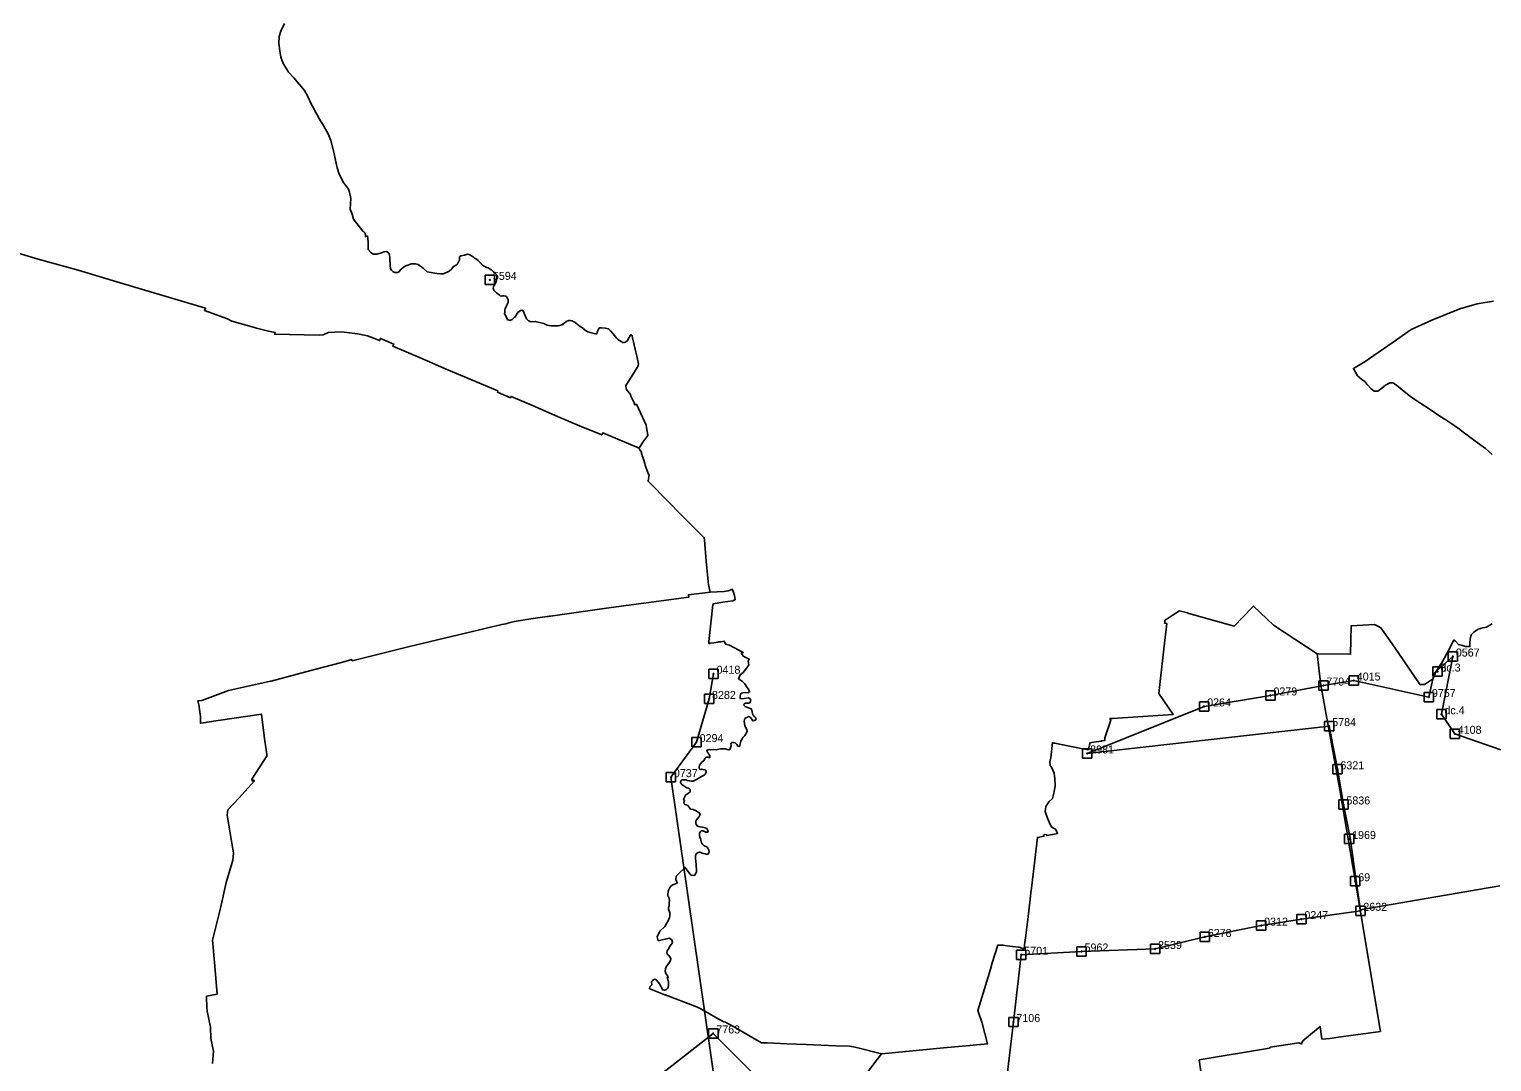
# Model space of a CAD drawing. Extents: x 462479 to 502016, y 241775 to 305873.
# Drawn here: x 475403 to 486368, y 272494 to 280240 of the extents above; entities that cross this region are included whole.
import ezdxf

# ---------------------------------------------------------------- set-up
doc = ezdxf.new("R2010")
doc.units = 0
for name, color, linetype in [('Default', 7, 'Continuous'), ('Level 19', 7, 'Continuous'), ('Level 51', 7, 'Continuous'), ('novada_robeza', 7, 'Continuous'), ('pagastu_robezas', 7, 'Continuous')]:
    doc.layers.add(name, color=color, linetype=linetype)

msp = doc.modelspace()

# ---------------------------------------------------------------- linework, layer by layer
at = {"layer": 'Default'}
for points in [[(466551, 278322), (476083, 271265), (477799, 272087), (478457, 271911), (479001, 271766), (479184, 271750), (479406, 271913), (479591, 272067), (480062, 272337), (480532, 272706), (480863, 272374), (480572, 271840), (481408, 272070), (480814, 270463), (480214, 274629), (480407, 274892), (480500, 275216), (480534, 275405)], [(482721, 272268), (482782, 272792), (482841, 273296), (483293, 273321), (483844, 273340), (484217, 273430), (484639, 273515), (484941, 273564), (485383, 273626), (485352, 273852), (485307, 274173), (485256, 274424), (485211, 274688), (485150, 275012), (483335, 274807), (484212, 275160), (484709, 275242), (485106, 275316), (485334, 275354), (485897, 275230), (485936, 275408), (486077, 275534), (485991, 275101), (486091, 274954), (486436, 274835)]]:
    msp.add_lwpolyline(points, dxfattribs=at)
at = {"layer": 'Level 19'}
for p, q in [((478822, 278395), (478892, 278395)), ((478822, 278325), (478822, 278395)), ((478892, 278325), (478822, 278325)), ((478892, 278395), (478892, 278325)), ((486041, 275569), (486111, 275569)), ((486041, 275499), (486041, 275569)), ((486042, 275569), (486112, 275569)), ((486042, 275499), (486042, 275569)), ((486111, 275569), (486111, 275499)), ((486112, 275569), (486112, 275499)), ((485926, 275456), (485996, 275456)), ((485926, 275386), (485926, 275456)), ((485926, 275456), (485996, 275456)), ((485926, 275386), (485926, 275456)), ((485926, 275456), (485996, 275456)), ((485926, 275386), (485926, 275456)), ((485927, 275456), (485997, 275456)), ((485927, 275386), (485927, 275456)), ((485996, 275456), (485996, 275386)), ((485996, 275456), (485996, 275386)), ((485996, 275456), (485996, 275386)), ((485997, 275456), (485997, 275386)), ((486111, 275499), (486041, 275499)), ((486112, 275499), (486042, 275499)), ((480499, 275440), (480569, 275440)), ((480499, 275370), (480499, 275440)), ((480569, 275370), (480499, 275370)), ((480569, 275440), (480569, 275370)), ((485071, 275351), (485141, 275351)), ((485071, 275281), (485071, 275351)), ((485071, 275351), (485141, 275351)), ((485071, 275281), (485071, 275351)), ((485071, 275351), (485141, 275351)), ((485071, 275281), (485071, 275351)), ((485071, 275351), (485141, 275351)), ((485071, 275281), (485071, 275351)), ((485141, 275351), (485141, 275281)), ((485141, 275351), (485141, 275281)), ((485141, 275351), (485141, 275281)), ((485141, 275351), (485141, 275281)), ((485299, 275389), (485369, 275389)), ((485299, 275319), (485299, 275389)), ((485369, 275389), (485369, 275319)), ((485996, 275386), (485926, 275386)), ((485996, 275386), (485926, 275386)), ((485996, 275386), (485926, 275386)), ((485997, 275386), (485927, 275386)), ((480465, 275251), (480535, 275251)), ((480465, 275181), (480465, 275251)), ((480535, 275251), (480535, 275181)), ((484674, 275277), (484744, 275277)), ((484674, 275207), (484674, 275277)), ((484744, 275277), (484744, 275207)), ((485141, 275281), (485071, 275281)), ((485141, 275281), (485071, 275281)), ((485141, 275281), (485071, 275281)), ((485141, 275281), (485071, 275281)), ((485369, 275319), (485299, 275319)), ((485862, 275265), (485932, 275265)), ((485862, 275195), (485862, 275265)), ((485862, 275265), (485932, 275265)), ((485862, 275195), (485862, 275265)), ((485862, 275265), (485932, 275265)), ((485862, 275195), (485862, 275265)), ((485932, 275265), (485932, 275195)), ((485932, 275265), (485932, 275195)), ((485932, 275265), (485932, 275195)), ((480535, 275181), (480465, 275181)), ((484177, 275195), (484247, 275195)), ((484177, 275125), (484177, 275195)), ((484247, 275125), (484177, 275125)), ((484247, 275195), (484247, 275125)), ((484744, 275207), (484674, 275207)), ((485932, 275195), (485862, 275195)), ((485932, 275195), (485862, 275195)), ((485932, 275195), (485862, 275195)), ((485956, 275136), (486026, 275136)), ((485956, 275066), (485956, 275136)), ((486026, 275136), (486026, 275066)), ((485115, 275047), (485185, 275047)), ((485115, 274977), (485115, 275047)), ((485185, 275047), (485185, 274977)), ((486026, 275066), (485956, 275066)), ((480372, 274927), (480442, 274927)), ((480372, 274857), (480372, 274927)), ((480442, 274927), (480442, 274857)), ((485185, 274977), (485115, 274977)), ((486056, 274989), (486126, 274989)), ((486056, 274919), (486056, 274989)), ((486056, 274989), (486126, 274989)), ((486056, 274919), (486056, 274989)), ((486056, 274989), (486126, 274989)), ((486056, 274919), (486056, 274989)), ((486126, 274919), (486056, 274919)), ((486126, 274919), (486056, 274919)), ((486126, 274919), (486056, 274919)), ((486126, 274989), (486126, 274919)), ((486126, 274989), (486126, 274919)), ((486126, 274989), (486126, 274919)), ((480442, 274857), (480372, 274857)), ((483300, 274842), (483370, 274842)), ((483300, 274772), (483300, 274842)), ((483370, 274842), (483370, 274772)), ((483370, 274772), (483300, 274772)), ((485176, 274723), (485246, 274723)), ((485176, 274653), (485176, 274723)), ((485246, 274723), (485246, 274653)), ((480179, 274664), (480249, 274664)), ((480179, 274594), (480179, 274664)), ((480249, 274594), (480179, 274594)), ((480249, 274664), (480249, 274594)), ((485246, 274653), (485176, 274653)), ((485221, 274459), (485291, 274459)), ((485221, 274389), (485221, 274459)), ((485291, 274459), (485291, 274389)), ((485291, 274389), (485221, 274389)), ((485264, 274200), (485334, 274200)), ((485264, 274130), (485264, 274200)), ((485334, 274130), (485264, 274130)), ((485334, 274200), (485334, 274130)), ((485310, 273883), (485380, 273883)), ((485310, 273813), (485310, 273883)), ((485380, 273813), (485310, 273813)), ((485380, 273883), (485380, 273813)), ((484906, 273599), (484976, 273599)), ((484906, 273529), (484906, 273599)), ((484976, 273599), (484976, 273529)), ((485348, 273661), (485418, 273661)), ((485348, 273591), (485348, 273661)), ((485418, 273591), (485348, 273591)), ((485418, 273661), (485418, 273591)), ((484604, 273550), (484674, 273550)), ((484604, 273480), (484604, 273550)), ((484674, 273480), (484604, 273480)), ((484674, 273550), (484674, 273480)), ((484976, 273529), (484906, 273529)), ((483809, 273375), (483879, 273375)), ((483809, 273305), (483809, 273375)), ((483879, 273375), (483879, 273305)), ((484182, 273465), (484252, 273465)), ((484182, 273395), (484182, 273465)), ((484252, 273395), (484182, 273395)), ((484252, 273465), (484252, 273395)), ((482806, 273331), (482876, 273331)), ((482806, 273261), (482806, 273331)), ((482806, 273331), (482876, 273331)), ((482806, 273261), (482806, 273331)), ((482876, 273261), (482806, 273261)), ((482876, 273261), (482806, 273261)), ((482876, 273331), (482876, 273261)), ((482876, 273331), (482876, 273261)), ((483258, 273356), (483328, 273356)), ((483258, 273286), (483258, 273356)), ((483328, 273286), (483258, 273286)), ((483328, 273356), (483328, 273286)), ((483879, 273305), (483809, 273305)), ((482747, 272827), (482817, 272827)), ((482747, 272757), (482747, 272827)), ((482747, 272827), (482817, 272827)), ((482747, 272757), (482747, 272827)), ((482747, 272827), (482817, 272827)), ((482747, 272757), (482747, 272827)), ((482817, 272827), (482817, 272757)), ((482817, 272827), (482817, 272757)), ((482817, 272827), (482817, 272757)), ((480497, 272741), (480567, 272741)), ((480497, 272671), (480497, 272741)), ((480567, 272741), (480567, 272671)), ((482817, 272757), (482747, 272757)), ((482817, 272757), (482747, 272757)), ((482817, 272757), (482747, 272757)), ((480567, 272671), (480497, 272671))]:
    msp.add_line(p, q, dxfattribs=at)
for centre in [(478857, 278360), (486077, 275534), (486076, 275534), (480534, 275405), (485334, 275354), (485962, 275421), (485961, 275421), (485961, 275421), (485961, 275421), (484709, 275242), (485106, 275316), (485106, 275316), (485106, 275316), (485106, 275316), (485897, 275230), (485897, 275230), (485897, 275230), (480500, 275216), (484212, 275160), (485150, 275012), (485991, 275101), (486091, 274954), (486091, 274954), (486091, 274954), (480407, 274892), (483335, 274807), (485211, 274688), (480215, 274628), (485256, 274424), (485299, 274165), (485345, 273848), (485383, 273626), (484639, 273515), (484941, 273564), (484217, 273430), (482841, 273296), (482841, 273296), (483293, 273321), (483844, 273340), (480532, 272706), (482782, 272792), (482782, 272792), (482782, 272792)]:
    msp.add_circle(centre, 3.5, dxfattribs=at)
at = {"layer": 'novada_robeza'}
for points in [[(477317, 280283), (477290, 280227), (477278, 280186), (477275, 280134), (477282, 280077), (477290, 280031), (477308, 279984), (477345, 279923), (477348, 279917), (477387, 279876), (477467, 279780), (477490, 279741), (477505, 279709), (477520, 279675), (477534, 279650), (477542, 279633), (477568, 279586), (477575, 279573), (477591, 279546), (477609, 279518), (477615, 279508), (477645, 279455), (477665, 279406), (477686, 279319), (477699, 279259), (477711, 279200), (477727, 279152), (477759, 279090), (477796, 279040), (477805, 279018), (477813, 278971), (477811, 278931), (477810, 278890), (477823, 278853), (477835, 278816), (477870, 278771), (477904, 278726), (477907, 278724), (477909, 278722), (477912, 278720), (477914, 278718), (477917, 278716), (477919, 278714), (477920, 278711), (477921, 278709), (477922, 278707), (477922, 278706), (477922, 278704), (477923, 278700), (477923, 278693), (477923, 278685), (477938, 278690), (477944, 278646), (477944, 278587), (477963, 278565), (477981, 278553), (478010, 278553), (478036, 278560), (478064, 278570), (478082, 278572), (478094, 278565), (478104, 278549), (478107, 278522), (478108, 278465), (478111, 278445), (478118, 278433), (478128, 278422), (478143, 278415), (478166, 278415), (478175, 278420), (478191, 278439), (478209, 278456), (478226, 278466), (478268, 278479), (478299, 278480), (478319, 278474), (478357, 278448), (478387, 278421), (478459, 278407), (478489, 278405), (478509, 278404), (478552, 278425), (478571, 278442), (478584, 278459), (478612, 278474), (478623, 278499), (478629, 278506), (478629, 278521), (478629, 278532), (478640, 278539), (478667, 278546), (478688, 278552), (478701, 278549), (478714, 278543), (478732, 278532), (478742, 278523), (478756, 278515), (478768, 278506), (478775, 278500), (478777, 278497), (478784, 278490), (478791, 278481), (478802, 278471), (478809, 278465), (478820, 278459), (478835, 278452), (478843, 278449), (478852, 278446), (478860, 278440), (478868, 278435), (478885, 278421), (478895, 278412), (478903, 278402), (478909, 278389), (478909, 278378), (478907, 278360), (478905, 278347), (478897, 278329), (478888, 278317), (478883, 278308), (478882, 278298), (478883, 278291), (478887, 278282), (478895, 278274), (478906, 278263), (478916, 278256), (478926, 278248), (478935, 278241), (478946, 278238), (478955, 278240), (478962, 278240), (478974, 278238), (478981, 278234), (478983, 278229), (478990, 278221), (478993, 278212), (478994, 278207), (478994, 278202), (478993, 278193), (478989, 278181), (478984, 278171), (478978, 278158), (478972, 278146), (478970, 278136), (478968, 278118), (478967, 278104), (478973, 278094), (478980, 278083), (478986, 278070), (478987, 278062), (478995, 278059), (479007, 278056), (479023, 278062), (479031, 278071), (479041, 278079), (479045, 278082), (479050, 278085), (479052, 278090), (479054, 278095), (479055, 278099), (479060, 278108), (479065, 278114), (479075, 278122), (479086, 278129), (479096, 278133), (479106, 278127), (479132, 278068), (479147, 278053), (479166, 278046), (479197, 278048), (479261, 278032), (479285, 278021), (479301, 278018), (479314, 278015), (479321, 278015), (479333, 278014), (479347, 278016), (479368, 278014), (479381, 278017), (479394, 278022), (479402, 278023), (479407, 278031), (479415, 278037), (479426, 278042), (479432, 278050), (479442, 278053), (479449, 278056), (479457, 278056), (479473, 278052), (479482, 278047), (479493, 278042), (479499, 278037), (479508, 278031), (479514, 278025), (479521, 278019), (479533, 278010), (479547, 278003), (479558, 277994), (479564, 277988), (479573, 277981), (479576, 277979), (479583, 277974), (479591, 277971), (479609, 277965), (479648, 277955), (479659, 277955), (479662, 277965), (479667, 277979), (479672, 277990), (479675, 277997), (479682, 278000), (479693, 278000), (479722, 277998), (479747, 277993), (479762, 277977), (479779, 277958), (479793, 277940), (479804, 277926), (479816, 277913), (479840, 277897), (479845, 277894), (479850, 277891), (479864, 277889), (479873, 277893), (479888, 277906), (479902, 277928), (479912, 277946), (479914, 277949), (479917, 277946), (479924, 277941), (479926, 277926), (479946, 277841), (479951, 277817), (479960, 277777), (479971, 277730), (479969, 277716), (479920, 277638), (479875, 277568), (479878, 277543), (479882, 277538), (479901, 277513), (479911, 277500), (479914, 277488), (479927, 277463), (479939, 277438), (479944, 277422), (479955, 277427), (480001, 277330), (480006, 277319), (480029, 277271), (480040, 277193), (480003, 277143), (479975, 277096)], [(486372, 277049), (486347, 277071), (486322, 277094), (486287, 277120), (486194, 277187), (486188, 277191), (486163, 277210), (486142, 277226), (486124, 277241), (486105, 277255), (486070, 277280), (486025, 277310), (485978, 277337), (485939, 277365), (485900, 277393), (485865, 277415), (485830, 277438), (485792, 277462), (485759, 277486), (485712, 277522), (485667, 277561), (485630, 277588), (485604, 277588), (485572, 277571), (485543, 277548), (485514, 277526), (485486, 277526), (485464, 277542), (485431, 277578), (485417, 277597), (485395, 277612), (485361, 277640), (485331, 277695), (485418, 277747), (485654, 277910), (485765, 277987), (485918, 278058), (486128, 278142), (486258, 278179), (486382, 278201)], [(479975, 277096), (479978, 277087), (479995, 277065), (479994, 277061), (479994, 277056), (480008, 277014), (480018, 276981), (480022, 276970), (480024, 276963), (480037, 276928), (480046, 276902), (480046, 276900), (480046, 276898), (480052, 276897), (480048, 276885), (480048, 276881), (480044, 276853), (480043, 276849), (480090, 276801), (480148, 276742), (480164, 276726), (480322, 276567), (480450, 276437), (480464, 276425), (480465, 276409), (480478, 276250), (480493, 276098), (480493, 276090), (480495, 276074), (480508, 276018)], [(480508, 276018), (480613, 276021), (480642, 276026), (480670, 276037), (480672, 276038), (480674, 276039), (480682, 276016), (480690, 275993), (480693, 275977), (480695, 275960), (480687, 275957), (480679, 275953), (480604, 275941), (480530, 275929), (480530, 275925), (480529, 275922), (480514, 275784), (480499, 275646), (480499, 275643), (480498, 275637), (480498, 275632), (480502, 275632), (480507, 275632), (480507, 275632), (480507, 275633), (480536, 275637), (480565, 275642), (480572, 275643), (480587, 275645), (480614, 275649), (480622, 275626), (480652, 275620), (480756, 275565), (480741, 275561), (480756, 275537), (480790, 275519), (480797, 275516), (480801, 275513), (480792, 275499), (480797, 275472), (480783, 275448), (480755, 275414), (480732, 275397), (480720, 275367), (480751, 275346), (480765, 275332), (480780, 275308), (480799, 275283), (480804, 275268), (480791, 275262), (480774, 275263), (480753, 275261), (480741, 275259), (480736, 275252), (480733, 275237), (480734, 275221), (480736, 275217), (480762, 275219), (480796, 275223), (480805, 275219), (480811, 275211), (480812, 275205), (480809, 275194), (480805, 275187), (480797, 275185), (480772, 275184), (480764, 275178), (480761, 275168), (480771, 275158), (480787, 275152), (480811, 275143), (480816, 275142), (480821, 275128), (480828, 275096), (480836, 275088), (480841, 275082), (480849, 275077), (480850, 275071), (480850, 275064), (480848, 275057), (480841, 275055), (480834, 275053), (480827, 275051), (480813, 275075), (480801, 275083), (480787, 275080), (480769, 275068), (480762, 275050), (480769, 275013), (480783, 274986), (480786, 274974), (480780, 274961), (480779, 274960), (480774, 274950), (480769, 274941), (480766, 274939), (480765, 274937), (480763, 274936), (480752, 274926), (480747, 274917), (480738, 274900), (480733, 274880), (480730, 274869), (480727, 274857), (480716, 274861), (480708, 274873), (480701, 274881), (480695, 274887), (480683, 274890), (480670, 274889), (480666, 274884), (480664, 274879), (480666, 274870), (480666, 274863), (480661, 274849), (480657, 274841), (480653, 274835), (480646, 274835), (480636, 274836), (480622, 274841), (480585, 274841), (480572, 274838), (480554, 274834), (480533, 274837), (480513, 274833), (480501, 274836), (480486, 274832), (480483, 274823), (480490, 274813), (480497, 274804), (480505, 274791), (480507, 274781), (480503, 274775), (480494, 274778), (480478, 274779), (480469, 274770), (480464, 274756), (480444, 274739), (480429, 274718), (480425, 274706), (480425, 274698), (480428, 274690), (480438, 274686), (480443, 274689), (480468, 274685), (480477, 274679), (480478, 274667), (480477, 274660), (480472, 274652), (480463, 274645), (480443, 274634), (480419, 274620), (480405, 274612), (480381, 274598), (480368, 274598), (480355, 274601), (480339, 274605), (480327, 274608), (480316, 274610), (480296, 274610), (480291, 274605), (480286, 274595), (480286, 274588), (480292, 274579), (480299, 274572), (480312, 274564), (480334, 274550), (480347, 274547), (480357, 274540), (480359, 274536), (480359, 274526), (480358, 274518), (480347, 274510), (480337, 274502), (480331, 274498), (480323, 274495), (480321, 274489), (480315, 274478), (480311, 274466), (480309, 274460), (480316, 274454), (480313, 274446), (480310, 274439), (480313, 274429), (480319, 274423), (480329, 274422), (480340, 274417), (480348, 274406), (480361, 274389), (480380, 274386), (480398, 274379), (480418, 274366), (480428, 274358), (480433, 274352), (480430, 274343), (480426, 274333), (480418, 274323), (480407, 274308), (480400, 274299), (480402, 274287), (480404, 274274), (480414, 274261), (480431, 274255), (480451, 274253), (480471, 274248), (480483, 274243), (480494, 274224), (480489, 274216), (480477, 274216), (480457, 274226), (480441, 274225), (480434, 274218), (480428, 274205), (480428, 274190), (480430, 274179), (480435, 274166), (480443, 274136), (480452, 274125), (480460, 274117), (480469, 274112), (480479, 274108), (480488, 274101), (480496, 274086), (480500, 274074), (480501, 274065), (480497, 274058), (480491, 274051), (480484, 274049), (480471, 274053), (480458, 274056), (480448, 274059), (480434, 274066), (480426, 274066), (480419, 274064), (480412, 274058), (480402, 274051), (480400, 274047), (480398, 274041), (480399, 274016), (480399, 274014), (480400, 274003), (480405, 273930), (480406, 273916), (480391, 273890), (480364, 273893), (480320, 273952), (480272, 273903), (480254, 273885), (480250, 273861), (480261, 273837), (480260, 273834), (480242, 273825), (480224, 273819), (480214, 273811), (480207, 273800), (480199, 273786), (480194, 273772), (480192, 273752), (480190, 273737), (480199, 273729), (480204, 273705), (480201, 273686), (480201, 273665), (480195, 273651), (480197, 273638), (480206, 273610), (480206, 273587), (480204, 273575), (480197, 273556), (480169, 273509), (480130, 273474), (480111, 273432), (480119, 273402), (480202, 273422), (480221, 273409), (480226, 273392), (480224, 273383), (480217, 273373), (480207, 273360), (480198, 273343), (480186, 273325), (480184, 273313), (480186, 273302), (480195, 273293), (480209, 273279), (480213, 273267), (480211, 273254), (480203, 273240), (480179, 273206), (480174, 273190), (480171, 273173), (480177, 273157), (480187, 273143), (480194, 273126), (480186, 273128), (480193, 273102), (480195, 273096), (480196, 273079), (480197, 273068), (480194, 273052), (480188, 273044), (480182, 273036), (480168, 273032), (480164, 273031), (480150, 273034), (480130, 273076), (480104, 273109), (480094, 273114), (480085, 273112), (480075, 273103), (480069, 273095), (480070, 273070), (480057, 273056), (480053, 273042), (480056, 273040), (480069, 273036), (480169, 272997), (480171, 272997), (480212, 272981), (480263, 272961), (480289, 272951), (480414, 272903), (480429, 272895), (480574, 272812), (480611, 272794), (480624, 272791), (480712, 272740), (480828, 272672), (480892, 272636), (480938, 272635), (480985, 272633), (481084, 272629), (481228, 272623), (481450, 272614), (481553, 272610), (481595, 272603), (481793, 272553)], [(485060, 275555), (484731, 275768), (484582, 275912), (484570, 275899), (484438, 275761), (484188, 275832), (484143, 275845), (484098, 275858), (484087, 275861), (484026, 275878), (483973, 275842), (483926, 275811), (483918, 275806), (483916, 275784), (483931, 275782), (483909, 275591), (483873, 275257), (483979, 275099), (483525, 275068), (483506, 275068), (483513, 275057), (483468, 274924), (483467, 274903), (483446, 274901), (483441, 274900), (483386, 274892), (483356, 274887), (483355, 274882), (483346, 274834), (483340, 274835), (483331, 274836), (483302, 274842), (483153, 274872), (483092, 274884), (483086, 274885), (483078, 274887), (483074, 274888), (483062, 274774), (483055, 274744), (483058, 274716), (483069, 274699), (483087, 274660), (483093, 274616), (483095, 274566), (483088, 274519), (483075, 274469), (483047, 274445), (483026, 274408), (483022, 274389), (483020, 274372), (483037, 274322), (483059, 274269), (483071, 274254), (483100, 274236), (483106, 274223), (483113, 274207), (483103, 274204), (483032, 274190), (483033, 274195), (483013, 274199), (483011, 274186), (482962, 274177), (482937, 273964), (482925, 273858), (482917, 273795), (482917, 273794), (482916, 273784), (482908, 273714), (482889, 273562), (482882, 273505), (482874, 273442), (482866, 273370), (482862, 273342), (482858, 273342), (482826, 273353), (482819, 273354), (482817, 273354), (482755, 273362), (482718, 273367), (482706, 273368), (482665, 273369), (482623, 273236), (482609, 273189), (482565, 273042), (482516, 272878), (482548, 272782), (482587, 272628), (482538, 272623), (482530, 272623), (482455, 272616), (482257, 272597), (481796, 272552), (481793, 272553)], [(485060, 275555), (485070, 275555), (485310, 275551), (485314, 275765), (485402, 275770), (485490, 275774), (485514, 275762), (485537, 275750), (485604, 275654), (485672, 275557), (485752, 275439), (485832, 275322), (485833, 275322), (485834, 275323), (485864, 275324), (485917, 275358), (485926, 275364), (485948, 275420), (485996, 275492), (486044, 275579), (486083, 275657), (486097, 275649), (486118, 275624), (486148, 275616), (486171, 275609), (486197, 275608), (486204, 275608), (486204, 275633), (486206, 275664), (486211, 275686), (486216, 275698), (486232, 275714), (486266, 275739), (486301, 275748), (486328, 275755), (486355, 275768), (486371, 275779)]]:
    msp.add_lwpolyline(points, dxfattribs=at)
at = {"layer": 'pagastu_robezas'}
for points in [[(479975, 277096), (479703, 277212), (479696, 277196), (479528, 277266), (479364, 277336), (479175, 277417), (479016, 277485), (479011, 277475), (478913, 277517), (478917, 277527), (478714, 277613), (478530, 277690), (478347, 277769), (478129, 277862), (478136, 277878), (478037, 277920), (478030, 277904), (477979, 277926), (477940, 277939), (477864, 277955), (477745, 277970), (477645, 277965), (477607, 277947), (477577, 277944), (477465, 277948), (477354, 277950), (477244, 277952), (477247, 277964), (477197, 277975), (477108, 277997), (477092, 278002), (476923, 278051), (476890, 278068), (476717, 278129), (476725, 278148), (476085, 278338), (475769, 278432), (475470, 278515), (475238, 278586)], [(480508, 276018), (480347, 275998), (480349, 275980), (480066, 275942), (479749, 275900), (479310, 275837), (479305, 275837), (479292, 275834), (479287, 275834), (479164, 275816), (479041, 275798), (479009, 275789), (478976, 275779), (478946, 275775), (478570, 275685), (478243, 275606), (477823, 275502), (477821, 275511), (477743, 275490), (477610, 275454), (477477, 275418), (477217, 275350), (477215, 275349), (477213, 275349), (476896, 275280), (476698, 275205), (476674, 275202), (476667, 275201), (476676, 275161), (476677, 275153), (476688, 275085), (476686, 275033), (476726, 275040), (476734, 275041), (477127, 275099), (477144, 275102), (477165, 274940), (477165, 274936), (477185, 274799), (477186, 274791), (477073, 274613), (477076, 274600), (477088, 274607), (477091, 274601), (476975, 274472), (476893, 274384), (476886, 274345), (476934, 274059), (476929, 274006), (476880, 273839), (476838, 273646), (476777, 273407), (476792, 273239), (476811, 273000), (476733, 272985), (476733, 272979), (476735, 272904), (476737, 272873), (476762, 272754), (476765, 272667), (476784, 272574), (476776, 272480)], [(485381, 273633), (485227, 274550), (485087, 275320), (485060, 275555)], [(485381, 273633), (486428, 273813)], [(485381, 273633), (485534, 272721), (485218, 272677), (485153, 272667), (485095, 272664), (485082, 272758), (484951, 272650), (484943, 272627), (484926, 272632), (484921, 272635), (484708, 272603), (484701, 272596), (484175, 272508), (484208, 272284)], [(481793, 272553), (481649, 272362)]]:
    msp.add_lwpolyline(points, dxfattribs=at)

# ---------------------------------------------------------------- texts
at = {"layer": 'Level 51'}
for s, p in [(' 5594', (478857, 278360)), (' 0567', (486077, 275534)), (' 0567', (486076, 275534)), (' 0418', (480534, 275405)), (' dc.3', (485961, 275421)), (' dc.3', (485961, 275421)), (' dc.3', (485961, 275421)), (' 3', (485962, 275421)), (' 7794', (485106, 275316)), (' 7794', (485106, 275316)), (' 7794', (485106, 275316)), (' 7794', (485106, 275316)), (' 4015', (485334, 275354)), (' 8282', (480500, 275216)), (' 0279', (484709, 275242)), (' 9757', (485897, 275230)), (' 9757', (485897, 275230)), (' 9757', (485897, 275230)), (' 0264', (484212, 275160)), (' dc.4', (485991, 275101)), (' 5784', (485150, 275012)), (' 4108', (486091, 274954)), (' 4108', (486091, 274954)), (' 4108', (486091, 274954)), (' 0294', (480407, 274892)), (' 8981', (483335, 274807)), (' 0737', (480214, 274629)), (' 6321', (485211, 274688)), (' 5836', (485256, 274424)), (' 1969', (485299, 274165)), (' 69', (485345, 273848)), (' 0247', (484941, 273564)), (' 2632', (485383, 273626)), (' 6278', (484217, 273430)), (' 0312', (484639, 273515)), (' 5962', (483293, 273321)), (' 2539', (483844, 273340)), (' 5701', (482841, 273296)), (' 5701', (482841, 273296)), (' 7106', (482782, 272792)), (' 7106', (482782, 272792)), (' 7106', (482782, 272792)), (' 7763', (480532, 272706))]:
    msp.add_text(s, height=60, dxfattribs=at).set_placement(p)

doc.saveas('drawing.dxf')
